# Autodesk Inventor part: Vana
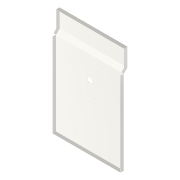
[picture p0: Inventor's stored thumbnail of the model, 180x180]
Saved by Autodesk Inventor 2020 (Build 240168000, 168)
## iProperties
Created: 2025-03
Part Number: Vana
Material: Ocel
Document SubType Name: Modeling
Designer: doma
Density: 7.85 g/cm^3
Appearance: Ocel
Author: doma
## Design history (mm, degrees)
sketch "Náčrt1"
  geometry: L1 (-280, -435)-(280, -435); L2 (280, -435)-(280, 435); L3 (280, 435)-(-280, 435); L4 (-280, 435)-(-280, -435); L5 (-280, -435)-(280, 435); L6 (280, -435)-(-280, 435); 1 further point
  constraints: 12 end point, 2 midpoint, 2 parallel, 1 horizontal, 1 perpendicular
  dimensions: "d0" = 560 distance of L3.end L2.end; "d1" = 870 distance of L2.end L1.end
extrude "Vysunutí1" new body sketch "Náčrt1" distance "d2" = 30; taper "d3" = 0 deg
sketch "Náčrt2"
  geometry: L1 (280, 435)-(280, -435) reference; L2 (-280, -435)-(-280, 435) reference; L3 (280, 435)-(-280, 435); L4 (-280, 435)-(-280, 285); L5 (-280, 285)-(280, 285); L6 (280, 285)-(280, 435); 3 further points
  constraints: 8 end point, 2 parallel, 1 horizontal, 1 perpendicular, 1 point on line
  dimensions: "d4" = 150 distance between parallel lines of L5 L3
extrude "Vysunutí2" join sketch "Náčrt2" distance "d5" = 30; taper "d6" = 0 deg
chamfer "Zkosení1" distance "d7" = 30; stored, may be unused: second distance "d8" = 2, angle "d9" = 45 deg
feature "Skořepina1" dims "d10" = 1.6
fillet "Zaoblení1" dims "d11" = 1
fillet "Zaoblení2" dims "d12" = 2.6
sketch "Náčrt3"
  geometry: L1 (0, 870)-(0, 0) reference; L2 (0, 870)-(-57.4, 870) reference; L3 (-27.4, 689.586)-(-30, 689.586) reference; L4 (-57.4, 721.077)-(-28.454, 692.131) reference; L5 (-30.293, 690.293)-(-9.08, 711.506); L6 (-30, 689.586)-(-30, 2.6) reference; L7 (-60, 721.077)-(-60, 867.4) reference; L8 (-60, 721.077)-(-30, 721.077); L9 (-59.238, 719.238)-(-38.025, 740.452); L10 (-21.213, 723.64)-(-9.08, 711.506); L11 (-30, 689.586)-(0, 689.586); L12 (-30, 870)-(-30, 744.853); L13 (-30, 744.853)-(-30, 712.653); L14 (-21.213, 723.64)-(-34.249, 736.675); A1 r 1 centre (-31, 689.586) between (-30, 689.586) and (-30.293, 690.293) reference; A2 r 31 centre (-31, 689.586) between (0, 689.586) and (-9.08, 711.506); A3 r 30 centre (0, 744.853) between (-30, 744.853) and (-21.213, 723.64); A4 r 3.6 centre (-31, 689.586) between (-27.4, 689.586) and (-28.454, 692.131) reference; A5 r 2.6 centre (-31, 689.586) between (-28.4, 689.586) and (-29.162, 691.424) reference; A6 r 2.6 centre (-31, 689.586) between (-28.4, 689.586) and (-29.162, 691.424) reference; 6 further points
  constraints: 16 end point, 4 point on circle, 3 point on line, 3 tangent, 2 centre point, 2 perpendicular, 2 vertical, 1 coincident, 1 horizontal
  dimensions: "d16" = 30 distance of L5.end L5.start; "d17" = 30 distance of L7.start L8.end; "d18" = 30 distance of L9.start L9.end; "d19" = 30 distance between parallel lines of L1 L12; "d20" = 30 radius of A3 (derived)
extrude "Vysunutí3" cut sketch "Náčrt3" extent not by distance; stored distance "d21" = 0; taper "d22" = 0 deg
sketch "Náčrt4"
  geometry: L1 (-2.6, -134.974)-(-2.6, 2.6) reference; L2 (-2.6, 2.6)-(557.4, 2.6) reference; C1 r 5 at (77.4, -77.4); 1 further point
  constraints: 1 centre point
  dimensions: "d23" = 10 diameter of C1; "d24" = 80 distance from line of L1 C1.centre; "d25" = 80 distance from line of L2 C1.centre
extrude "Vysunutí4" cut sketch "Náčrt4" distance "d26" = 10; taper "d27" = 0 deg
sketch "Náčrt7"
  geometry: L1 (-280, -435)-(280, -435) reference; L2 (280, -435)-(280, 254.586) reference; C1 r 17.5 at (97.5, -360); C2 r 10 at (55, -35) reference; C3 r 10 at (-55, -35) reference; C4 r 10 at (55, 175) reference; C5 r 10 at (-55, 175) reference; 1 further point
  constraints: 1 centre point
  dimensions: "d56" = 75 distance from line of L1 C1.centre; "d57" = 182.5 distance from line of L2 C1.centre
hole "Díra3" sketch "Náčrt7" diameter "d46" = 14; stored, may be unused: countersink angle "d50" = 90 deg, drill point angle "d52" = 118 deg; dims "d47" = 6, "d48" = 4, "d49" = 2, "d51" = 8
sketch "Náčrt8"
  geometry: C1 r 10 at (0, 70) reference; C2 r 20 at (0, 70); 1 further point
  constraints: 1 centre point, 1 coincident
  dimensions: "d53" = 40 diameter of C2
extrude "Vysunutí5" cut sketch "Náčrt8" distance "d54" = 10; taper "d55" = 0 deg
node "Těleso1"
node "Promítnutá smyčka1"
node "Referenční2"
node "Referenční3"
node "Referenční4"
node "Referenční5"
node "Referenční6"
